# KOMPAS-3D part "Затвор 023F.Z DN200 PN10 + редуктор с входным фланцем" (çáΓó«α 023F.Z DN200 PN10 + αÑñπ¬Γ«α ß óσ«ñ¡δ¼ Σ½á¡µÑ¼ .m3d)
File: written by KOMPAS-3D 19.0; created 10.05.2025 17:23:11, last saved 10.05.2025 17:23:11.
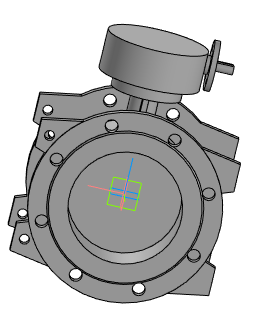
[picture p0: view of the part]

Document properties: Полное имя файла: Затвор 023F.Z DN200 PN10 + редуктор с входным фланцем .a3d

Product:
- Part/product: Затвор 023F.Z DN200 PN10 + редуктор с входным фланцем
    Масса: 60.4138

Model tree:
1. Операция без истории:1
